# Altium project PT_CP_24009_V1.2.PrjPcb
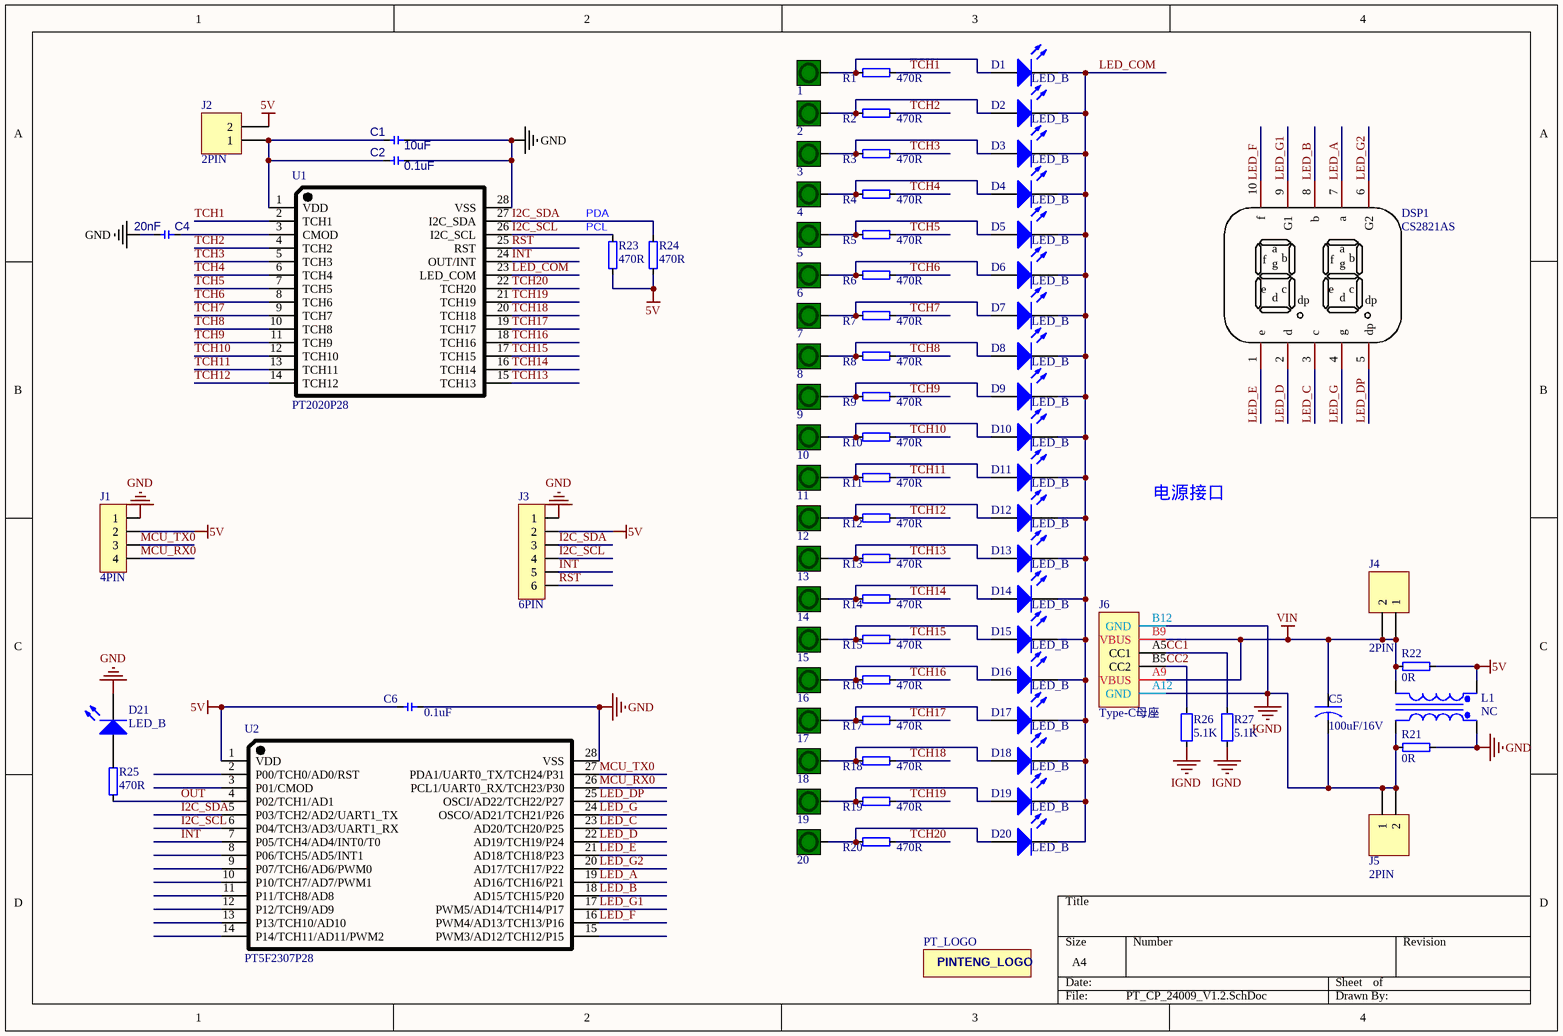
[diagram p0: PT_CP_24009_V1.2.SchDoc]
1 sheet, 84 parts. Net scope: global (net labels, ports and power ports of the same name join across sheets).
Board file: PT_CP_24009_V1.2.PcbDoc

## Sheet PT_CP_24009_V1.2.SchDoc
size A4; PageSetup: Record=PageOptions¦CenterHorizontal=True¦CenterVertical=True¦PrintScale=1.00¦XCorrection=1.00¦YCorrection=1.00¦PrintKind=1¦BorderSize=5000000¦LeftOffset=0¦BottomOffset=0¦Orientation=2¦PaperLength=1000¦PaperWidth=1000¦Scale=100¦PaperSource=7¦PrintQuality=1200¦MediaType=1¦DitherType=10¦PrintScaleMode=1¦PaperKind=A4¦PaperIndex=9

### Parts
1  DOWN  [TP_10mm - H]  (value not drawn)
2  DOWN  [TP_10mm - H]  (value not drawn)
3  DOWN  [TP_10mm - H]  (value not drawn)
4  DOWN  [TP_10mm - H]  (value not drawn)
5  DOWN  [TP_10mm - H]  (value not drawn)
6  DOWN  [TP_10mm - H]  (value not drawn)
7  DOWN  [TP_10mm - H]  (value not drawn)
8  DOWN  [TP_10mm - H]  (value not drawn)
9  DOWN  [TP_10mm - H]  (value not drawn)
10  DOWN  [TP_10mm - H]  (value not drawn)
11  DOWN  [TP_10mm - H]  (value not drawn)
12  DOWN  [TP_10mm - H]  (value not drawn)
13  DOWN  [TP_10mm - H]  (value not drawn)
14  DOWN  [TP_10mm - H]  (value not drawn)
15  DOWN  [TP_10mm - H]  (value not drawn)
16  DOWN  [TP_10mm - H]  (value not drawn)
17  DOWN  [TP_10mm - H]  (value not drawn)
18  DOWN  [TP_10mm - H]  (value not drawn)
19  DOWN  [TP_10mm - H]  (value not drawn)
20  DOWN  [TP_10mm - H]  (value not drawn)
C1  10uF  [C0805]
C2  0.1uF  [C0603]
C4  20nF  [C0603]
C5  100uF/16V  [CS5.0]
C6  0.1uF  [C0603]
D1  LED_B  [LED_0805_F]
D2  LED_B  [LED_0805_F]
D3  LED_B  [LED_0805_F]
D4  LED_B  [LED_0805_F]
D5  LED_B  [LED_0805_F]
D6  LED_B  [LED_0805_F]
D7  LED_B  [LED_0805_F]
D8  LED_B  [LED_0805_F]
D9  LED_B  [LED_0805_F]
D10  LED_B  [LED_0805_F]
D11  LED_B  [LED_0805_F]
D12  LED_B  [LED_0805_F]
D13  LED_B  [LED_0805_F]
D14  LED_B  [LED_0805_F]
D15  LED_B  [LED_0805_F]
D16  LED_B  [LED_0805_F]
D17  LED_B  [LED_0805_F]
D18  LED_B  [LED_0805_F]
D19  LED_B  [LED_0805_F]
D20  LED_B  [LED_0805_F]
D21  LED_B  [LED_0805]
DSP1  CS2821AS  [LED_2_0.28_2281]
J1  4PIN  [D2.54_4P]
J2  2PIN  [D2.54_2P]
J3  6PIN  [D2.54_6P]
J4  2PIN  [D2.54_2P]
J5  2PIN  [D2.54_2P]
J6  Type-C母座  [TYPE-C-6P]
L1  NC  [L_10*5]
PT_LOGO  PT_LOGO  [PT_LOGO_2]  (value not drawn)
R1  470R  [R0603]
R2  470R  [R0603]
R3  470R  [R0603]
R4  470R  [R0603]
R5  470R  [R0603]
R6  470R  [R0603]
R7  470R  [R0603]
R8  470R  [R0603]
R9  470R  [R0603]
R10  470R  [R0603]
R11  470R  [R0603]
R12  470R  [R0603]
R13  470R  [R0603]
R14  470R  [R0603]
R15  470R  [R0603]
R16  470R  [R0603]
R17  470R  [R0603]
R18  470R  [R0603]
R19  470R  [R0603]
R20  470R  [R0603]
R21  0R  [R0805]
R22  0R  [R0805]
R23  470R  [R0603]
R24  470R  [R0603]
R25  470R  [R0603]
R26  5.1K  [RES0603]
R27  5.1K  [RES0603]
U1  PT2020P28  [SSOP28_0.635]
U2  PT5F2307P28  [SSOP28_0.635]

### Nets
5V: C6.1 J1.2 J2.2 J3.2 L1.3(Sec+) R22.2 R23.2 R24.2 U2.1(VDD)
GND: C1.2 C2.2 C4.1 C6.2 D21.2(K) J1.1 J3.1 L1.1(Pri+) R21.2 U1.28(VSS) U2.28(VSS)
IGND: C5.2 J5.1 J5.2 J6.A12(GND) J6.B12(GND) L1.2(Pri-) R21.1 R26.1 R27.1
VIN: C5.1 J4.1 J4.2 J6.A9(VBUS) J6.B9(VBUS) L1.4(Sec-) R22.1
CC1: J6.A5(CC1) R27.2
CC2: J6.B5(CC2) R26.2
I2C_SCL: J3.4 R23.1 U1.26(I2C_SCL) U2.6(P04/TCH3/AD3/UART1_RX)
I2C_SDA: J3.3 R24.1 U1.27(I2C_SDA) U2.5(P03/TCH2/AD2/UART1_TX)
INT: J3.5 U1.24(OUT/INT) U2.7(P05/TCH4/AD4/INT0/T0)
LED_A: DSP1.7(a) U2.19(AD16/TCH16/P21)
LED_B: DSP1.8(b) U2.18(AD15/TCH15/P20)
LED_C: DSP1.3(c) U2.23(AD20/TCH20/P25)
LED_COM: D1.2(K) D2.2(K) D3.2(K) D4.2(K) D5.2(K) D6.2(K) D7.2(K) D8.2(K) D9.2(K) D10.2(K) D11.2(K) D12.2(K) D13.2(K) D14.2(K) D15.2(K) D16.2(K) D17.2(K) D18.2(K) D19.2(K) D20.2(K) U1.23(LED_COM)
LED_D: DSP1.2(d) U2.22(AD19/TCH19/P24)
LED_DP: DSP1.5(dp) U2.25(OSCI/AD22/TCH22/P27)
LED_E: DSP1.1(e) U2.21(AD18/TCH18/P23)
LED_F: DSP1.10(f) U2.16(PWM4/AD13/TCH13/P16)
LED_G: DSP1.4(g) U2.24(OSCO/AD21/TCH21/P26)
LED_G1: DSP1.9(G1) U2.17(PWM5/AD14/TCH14/P17)
LED_G2: DSP1.6(G2) U2.20(AD17/TCH17/P22)
MCU_RX0: J1.4 U2.26(PCL1/UART0_RX/TCH23/P30)
MCU_TX0: J1.3 U2.27(PDA1/UART0_TX/TCH24/P31)
OUT: R25.1 U2.4(P02/TCH1/AD1)
RST: J3.6 U1.25(RST)
TCH1: R1.2 U1.2(TCH1)
TCH2: R2.2 U1.4(TCH2)
TCH3: R3.2 U1.5(TCH3)
TCH4: R4.2 U1.6(TCH4)
TCH5: R5.2 U1.7(TCH5)
TCH6: R6.2 U1.8(TCH6)
TCH7: R7.2 U1.9(TCH7)
TCH8: R8.2 U1.10(TCH8)
TCH9: R9.2 U1.11(TCH9)
TCH10: R10.2 U1.12(TCH10)
TCH11: R11.2 U1.13(TCH11)
TCH12: R12.2 U1.14(TCH12)
TCH13: R13.2 U1.15(TCH13)
TCH14: R14.2 U1.16(TCH14)
TCH15: R15.2 U1.17(TCH15)
TCH16: R16.2 U1.18(TCH16)
TCH17: R17.2 U1.19(TCH17)
TCH18: R18.2 U1.20(TCH18)
TCH19: R19.2 U1.21(TCH19)
TCH20: R20.2 U1.22(TCH20)
Net1_1: 1.1 D1.1(A) R1.1
Net2_1: 2.1 D2.1(A) R2.1
Net3_1: 3.1 D3.1(A) R3.1
Net4_1: 4.1 D4.1(A) R4.1
Net5_1: 5.1 D5.1(A) R5.1
Net6_1: 6.1 D6.1(A) R6.1
Net7_1: 7.1 D7.1(A) R7.1
Net8_1: 8.1 D8.1(A) R8.1
Net9_1: 9.1 D9.1(A) R9.1
Net10_1: 10.1 D10.1(A) R10.1
Net11_1: 11.1 D11.1(A) R11.1
Net12_1: 12.1 D12.1(A) R12.1
Net13_1: 13.1 D13.1(A) R13.1
Net14_1: 14.1 D14.1(A) R14.1
Net15_1: 15.1 D15.1(A) R15.1
Net16_1: 16.1 D16.1(A) R16.1
Net17_1: 17.1 D17.1(A) R17.1
Net18_1: 18.1 D18.1(A) R18.1
Net19_1: 19.1 D19.1(A) R19.1
Net20_1: 20.1 D20.1(A) R20.1
NetC1_1: C1.1 C2.1 J2.1 U1.1(VDD)
NetC4_2: C4.2 U1.3(CMOD)
NetD21_1: D21.1(A) R25.2

Not connected (* = marked no-connect by the designer): U2 2(P00/TCH0/AD0/RST) 3(P01/CMOD) 8(P06/TCH5/AD5/INT1) 9(P07/TCH6/AD6/PWM0) 10(P10/TCH7/AD7/PWM1) 11(P11/TCH8/AD8) 12(P12/TCH9/AD9) 13(P13/TCH10/AD10) 14(P14/TCH11/AD11/PWM2) 15(PWM3/AD12/TCH12/P15)

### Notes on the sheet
- (near R23) PDA
- (near R23) PCL
- 电源接口

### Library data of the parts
1-20 = TOUCH_SM: TP
C1 C2 C4 = CAP3
C5 = CAP2: 电解电容
C6 = CAP1: 电容
D1-D21 = LED
DSP1 = LED_2: 2位数码管
J6 = Type-C-receptacle_6p: Type-C 6P直插
L1 = Trans Cupl: Transformer (Coupled Inductor Model)
R1-R25 = RES1: 电阻
R26 R27 = Res: Resistor
U1 = PT2020P28: 20键标品
U2 = PT109AP28: MCU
